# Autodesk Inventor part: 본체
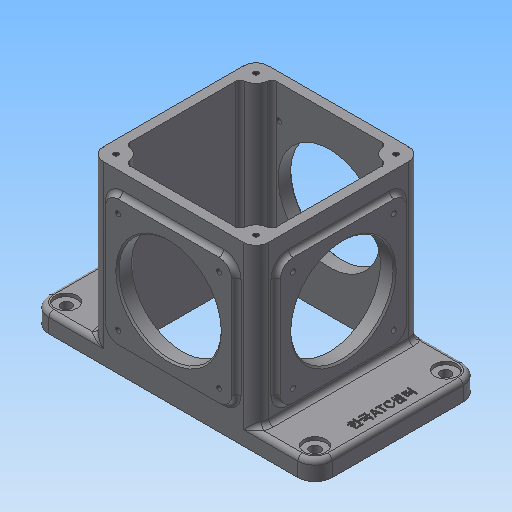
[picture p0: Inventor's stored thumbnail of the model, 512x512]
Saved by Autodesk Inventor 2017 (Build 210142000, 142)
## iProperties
Created: 2018-09
Part Number: 본체
Material: 일반
Document SubType Name: Modeling
Designer: mduedu
Density: 2.71 g/cm^3
Mass: 972.977 g
Surface Area: 957.184 cm^2
Volume: 359.032 cm^3
Appearance: 기본값
Author: mduedu
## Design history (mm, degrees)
sketch "스케치1"
  geometry: L1 (90, 52.5)-(-90, 52.5); L2 (-90, 52.5)-(-90, -52.5); L3 (-90, -52.5)-(90, -52.5); L4 (90, -52.5)-(90, 52.5); L5 (90, 52.5)-(-90, -52.5); L6 (-90, 52.5)-(90, -52.5); 1 further point
  constraints: 12 end point, 2 midpoint, 2 parallel, 1 horizontal, 1 perpendicular
  dimensions: "d0" = 180 distance of L3.end L2.end; "d1" = 105 distance of L2.end L1.end
extrude "돌출1" new body sketch "스케치1" distance "d2" = 12; taper "d3" = 0 deg
sketch "스케치2"
  geometry: L1 (-52.5, -52.5)-(52.5, -52.5); L2 (52.5, -52.5)-(52.5, 52.5); L3 (52.5, 52.5)-(-52.5, 52.5); L4 (-52.5, 52.5)-(-52.5, -52.5); L5 (-52.5, -52.5)-(52.5, 52.5); L6 (52.5, -52.5)-(-52.5, 52.5); 1 further point
  constraints: 12 end point, 2 midpoint, 2 parallel, 1 horizontal, 1 perpendicular
  dimensions: "d4" = 105 distance of L3.end L2.end; "d5" = 105 distance of L2.end L1.end
extrude "돌출2" join sketch "스케치2" distance "d6" = 100; taper "d7" = 0 deg
sketch "스케치14"
  geometry: L1 (-52.5, 52.5)-(52.5, 52.5) reference; L2 (52.5, 52.5)-(52.5, -52.5) reference; L3 (52.5, -52.5)-(-52.5, -52.5) reference; L4 (-52.5, -52.5)-(-52.5, 52.5) reference; L5 (46.5, 46.5)-(-46.5, 46.5); L6 (-46.5, 46.5)-(-46.5, -46.5); L7 (-46.5, -46.5)-(46.5, -46.5); L8 (46.5, -46.5)-(46.5, 46.5); 1 further point
  constraints: 8 end point, 3 other
  dimensions: "d85" = 6 distance between parallel lines of L5 L1
extrude "돌출10" cut sketch "스케치14" stored distance "d86" = 10; taper "d87" = 0 deg
fillet "모깎기1" dims "d12" = 8
sketch "스케치15"
  geometry: A1 r 8 centre (-44.5, 44.5) between (-44.5, 52.5) and (-52.5, 44.5) reference; A2 r 8 centre (44.5, 44.5) between (52.5, 44.5) and (44.5, 52.5) reference; A3 r 8 centre (44.5, -44.5) between (44.5, -52.5) and (52.5, -44.5) reference; A4 r 8 centre (-44.5, -44.5) between (-52.5, -44.5) and (-44.5, -52.5) reference; 5 further points
  constraints: 4 coincident, 4 vertical alignment, 8 other
extrude "돌출11" join sketch "스케치15" stored distance "d88" = 10; taper "d89" = 0 deg
fillet "모깎기15" dims "d90" = 3
sketch "스케치6"
  geometry: L1 (50, 19)-(130, 19); L2 (130, 19)-(130, 99); L3 (130, 99)-(50, 99); L4 (50, 99)-(50, 19); L5 (50, 19)-(130, 99); L6 (130, 19)-(50, 99); L7 (0, 0)-(180, 0) reference; 4 further points
  constraints: 12 end point, 4 midpoint, 2 parallel, 1 horizontal, 1 perpendicular, 1 vertical alignment
  dimensions: "d25" = 80 distance of L3.end L2.end; "d26" = 80 distance of L2.end L1.end; "d27" = 59 distance of point (90, 0) point (90, 59)
extrude "돌출6" join sketch "스케치6" distance "d28" = 3; taper "d29" = 0 deg
fillet "모깎기7" dims "d30" = 8
sketch "스케치7"
  geometry: C1 r 32.5 at (90, 59); 1 further point
  constraints: 1 centre point, 1 vertical alignment
  dimensions: "d32" = 65 diameter of C1; "d33" = 59 distance of C1.centre point (90, 0)
extrude "돌출7" cut sketch "스케치7" stored distance "d34" = 3; taper "d35" = 0 deg
fillet "모깎기9" dims "d36" = 3
sketch "스케치8"
  geometry: L1 (4.5, 7)-(84.5, 7); L2 (84.5, 7)-(84.5, 87); L3 (84.5, 87)-(4.5, 87); L4 (4.5, 87)-(4.5, 7); L5 (4.5, 7)-(84.5, 87); L6 (84.5, 7)-(4.5, 87); L7 (-8, -12)-(97, -12) reference; C1 r 32.5 at (44.5, 47); 4 further points
  constraints: 12 end point, 4 midpoint, 2 parallel, 1 centre point, 1 coincident, 1 horizontal, 1 perpendicular, 1 vertical alignment
  dimensions: "d37" = 80 distance of L3.end L2.end; "d38" = 80 distance of L2.end L1.end; "d39" = 59 distance from line of point (44.5, 47) L7; "d40" = 65 diameter of C1
extrude "돌출8" join sketch "스케치8" distance "d41" = 3; taper "d42" = 0 deg
fillet "모깎기10" dims "d43" = 8
extrude "돌출9" cut sketch "스케치8" stored distance "d44" = 3; taper "d45" = 0 deg
fillet "모깎기11" dims "d46" = 3
sketch "스케치9"
  geometry: L1 (50, 91)-(50, 27) reference; L2 (58, 19)-(122, 19) reference; L3 (130, 27)-(130, 91) reference; L4 (122, 99)-(58, 99) reference; C1 r 32.5 at (90, 59) reference; A1 r 8 centre (58, 91) between (58, 99) and (50, 91) reference; A2 r 8 centre (58, 27) between (50, 27) and (58, 19) reference; A3 r 8 centre (122, 27) between (122, 19) and (130, 27) reference; A4 r 8 centre (122, 91) between (130, 91) and (122, 99) reference; 5 further points
  constraints: 4 coincident
hole "구멍1" sketch "스케치9" at (58, 91), (122, 91), (122, 27), (58, 27) diameter "d47" = 3.242; stored, may be unused: countersink angle "d51" = 90 deg, drill point angle "d53" = 118 deg; dims "d48" = 6, "d49" = 4, "d50" = 2, "d52" = 9
sketch "스케치10"
  geometry: L1 (12.5, 7)-(76.5, 7) reference; L2 (84.5, 15)-(84.5, 79) reference; L3 (76.5, 87)-(12.5, 87) reference; L4 (4.5, 79)-(4.5, 15) reference; C1 r 32.5 at (44.5, 47) reference; A1 r 8 centre (12.5, 15) between (4.5, 15) and (12.5, 7) reference; A2 r 8 centre (76.5, 15) between (76.5, 7) and (84.5, 15) reference; A3 r 8 centre (76.5, 79) between (84.5, 79) and (76.5, 87) reference; A4 r 8 centre (12.5, 79) between (12.5, 87) and (4.5, 79) reference; 5 further points
  constraints: 4 coincident
hole "구멍2" sketch "스케치10" at (12.5, 79), (76.5, 79), (76.5, 15), (12.5, 15) diameter "d54" = 3.242; stored, may be unused: countersink angle "d58" = 90 deg, drill point angle "d60" = 118 deg; dims "d55" = 6, "d56" = 4, "d57" = 2, "d59" = 9
fillet "모깎기12" dims "d68" = 11
sketch "스케치16"
  geometry: A1 r 11 centre (-79, 41.5) between (-79, 52.5) and (-90, 41.5) reference; A2 r 11 centre (-79, -41.5) between (-90, -41.5) and (-79, -52.5) reference; A3 r 11 centre (79, 41.5) between (90, 41.5) and (79, 52.5) reference; A4 r 11 centre (79, -41.5) between (79, -52.5) and (90, -41.5) reference; 5 further points
  constraints: 4 coincident
hole "구멍5" sketch "스케치16" at (-79, 41.5), (79, 41.5), (79, -41.5), (-79, -41.5) diameter "d91" = 6.6; stored, may be unused: countersink angle "d95" = 90 deg, drill point angle "d97" = 118 deg; dims "d92" = 6, "d93" = 14, "d94" = 2, "d96" = 8
fillet "모깎기13" dims "d77" = 3
fillet "모깎기14" dims "d78" = 3
chamfer "모따기1" distance "d79" = 1; stored, may be unused: second distance "d80" = 2, angle "d81" = 45 deg
sketch "스케치17"
  geometry: A1 r 8 centre (-44.5, 44.5) between (-44.5, 52.5) and (-52.5, 44.5) reference; A2 r 8 centre (-44.5, -44.5) between (-52.5, -44.5) and (-44.5, -52.5) reference; A3 r 8 centre (44.5, -44.5) between (44.5, -52.5) and (52.5, -44.5) reference; A4 r 8 centre (44.5, 44.5) between (52.5, 44.5) and (44.5, 52.5) reference; 5 further points
  constraints: 4 coincident
hole "구멍6" sketch "스케치17" at (-44.5, 44.5), (44.5, 44.5), (44.5, -44.5), (-44.5, -44.5) diameter "d98" = 3.242; stored, may be unused: countersink angle "d102" = 90 deg, drill point angle "d104" = 118 deg; dims "d99" = 8, "d100" = 15, "d101" = 2, "d103" = 10
sketch "스케치13"
  geometry: L1 (90, -41.5)-(90, 41.5) reference; 2 further points
  constraints: 1 horizontal alignment, 1 other
  dimensions: "d82" = 10 distance from line of point (80, 0) L1
feature "엠보싱1" sketch "스케치13" dims "d0" = 180, "d1" = 105, "d25" = 80, "d26" = 80, "d27" = 59, "d83" = 0.5, "d84" = 0
node "솔리드1"
mirror "대칭1"
mirror "대칭2"
node "투영된 루프2"
node "투영된 루프3"
node "투영된 루프6"
